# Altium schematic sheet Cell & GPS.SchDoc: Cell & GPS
size 431 x 279 mm; DocumentNumber: 10000020916; Revision: 000; SheetNumber: 8; SheetTotal: 10; ProjectTitle: Industrial IOT Sensor
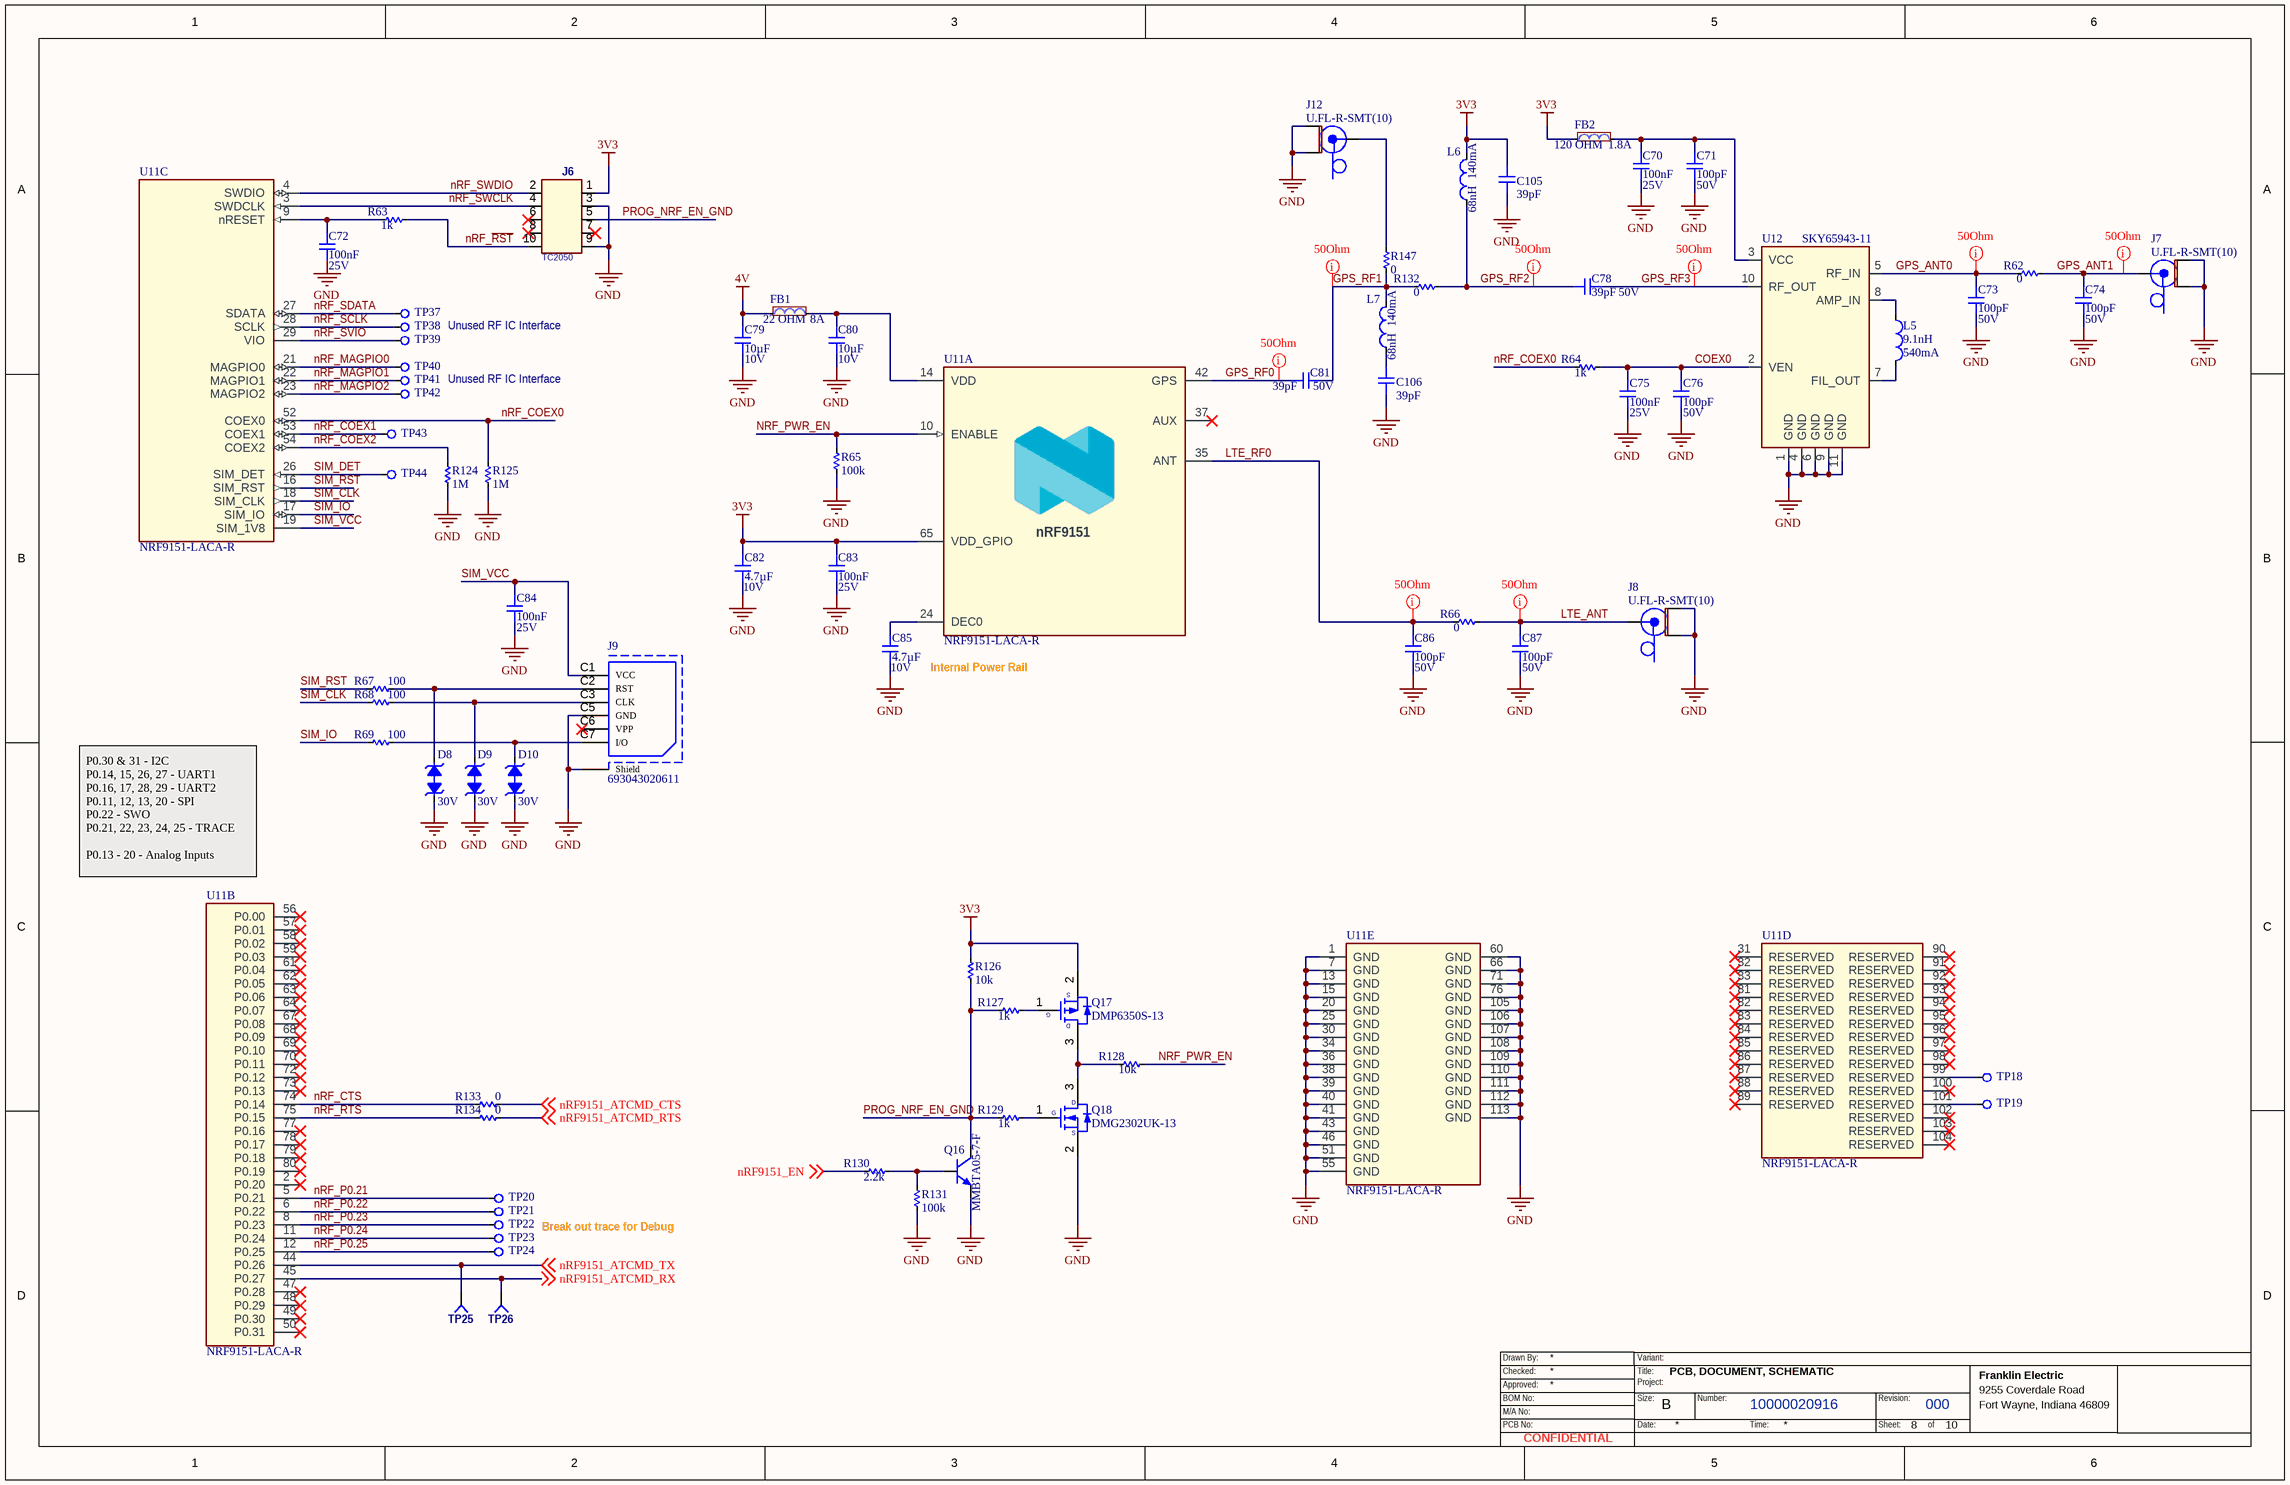
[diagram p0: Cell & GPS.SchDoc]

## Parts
C70  100nF  Voltage Rating DC: 25V  [CAPC1005X60N]
C71  100pF  Voltage Rating DC: 50V  [CAPC1005X60N]
C72  100nF  Voltage Rating DC: 25V  [CAPC1005X60N]
C73  100pF  Voltage Rating DC: 50V  [CAPC1005X60N]
C74  100pF  Voltage Rating DC: 50V  [CAPC1005X60N]
C75  100nF  Voltage Rating DC: 25V  [CAPC1005X60N]
C76  100pF  Voltage Rating DC: 50V  [CAPC1005X60N]
C78  39pF  Voltage Rating DC: 50V  [CAPC1005X60N]
C79  10µF  Voltage Rating DC: 10V  [CAPC1608X90N]
C80  10µF  Voltage Rating DC: 10V  [CAPC1608X90N]
C81  39pF  Voltage Rating DC: 50V  [CAPC1005X60N]
C82  4.7µF  Voltage Rating DC: 10V  [CAPC1005X60N]
C83  100nF  Voltage Rating DC: 25V  [CAPC1005X60N]
C84  100nF  Voltage Rating DC: 25V  [CAPC1005X60N]
C85  4.7µF  Voltage Rating DC: 10V  [CAPC1005X60N]
C86  100pF  Voltage Rating DC: 50V  [CAPC1005X60N]
C87  100pF  Voltage Rating DC: 50V  [CAPC1005X60N]
C105  39pF  [CAPC1005X60N]
C106  39pF  [CAPC1005X60N]
D8  Reverse Voltage: 30V  [SOD882-A]  (hidden comment: PESD30VF1BLYL)
D9  Reverse Voltage: 30V  [SOD882-A]  (hidden comment: PESD30VF1BLYL)
D10  Reverse Voltage: 30V  [SOD882-A]  (hidden comment: PESD30VF1BLYL)
FB1  22 OHM  Rated Current: 8A  [INDC1608X06N]
FB2  120 OHM  Rated Current: 1.8A  [FerriteBead_0402]
J6  value TC2050  [TC2050_NL]  (hidden comment: J_CONN TC2050)  (no BOM)
J7  U.FL-R-SMT(10)  [CONN U.FL RCPT]
J8  U.FL-R-SMT(10)  [CONN U.FL RCPT]
J9  693043020611  [Nano SIM Card]
J12  U.FL-R-SMT(10)  [CONN U.FL RCPT]
L5  9.1nH  Rated Current: 540mA  [IND0402-WIREWOUND-NO-MAGNETIC-N]
L6  68nH  Rated Current: 140mA  [IND0402-WIREWOUND-NO-MAGNETIC-N]
L7  68nH  Rated Current: 140mA  [IND0402-WIREWOUND-NO-MAGNETIC-N]
Q16  MMBTA05-7-F  [SOT90P225X100-3N]
Q17  DMP6350S-13  [SOT90P225X100-3N]
Q18  DMG2302UK-13  [SOT90P225X100-3N]
R62  0  [RESC1005N]
R63  1k  [RESC1005N]
R64  1k  [RESC1005N]
R65  100k  [RESC1005N]
R66  0  [RESC1005N]
R67  100  [RESC1005N]
R68  100  [RESC1005N]
R69  100  [RESC1005N]
R124  1M  [RESC1005N]
R125  1M  [RESC1005N]
R126  10k  [RESC1005N]
R127  1k  [RESC1005N]
R128  10k  [RESC1005N]
R129  1k  [RESC1005N]
R130  2.2k  [RESC1005N]
R131  100k  [RESC1005N]
R132  0  [RESC1005N]
R133  0  [RESC1005N]
R134  0  [RESC1005N]
R147  0  [RESC1005N]
TP18  Test Points  [TP040SMD]  (value not drawn)  (no BOM)
TP19  Test Points  [TP040SMD]  (value not drawn)  (no BOM)
TP20  Test Points  [TP040SMD]  (value not drawn)  (no BOM)
TP21  Test Points  [TP040SMD]  (value not drawn)  (no BOM)
TP22  Test Points  [TP040SMD]  (value not drawn)  (no BOM)
TP23  Test Points  [TP040SMD]  (value not drawn)  (no BOM)
TP24  Test Points  [TP040SMD]  (value not drawn)  (no BOM)
TP25  TEST POINT, SMD PAD, .050 DIA  [TESTPOINT_SMD_ROUND_50]  (value not drawn)
TP26  TEST POINT, SMD PAD, .050 DIA  [TESTPOINT_SMD_ROUND_50]  (value not drawn)
TP37  Test Points  [TP 10 Mils SMD]  (value not drawn)  (no BOM)
TP38  Test Points  [TP 10 Mils SMD]  (value not drawn)  (no BOM)
TP39  Test Points  [TP 10 Mils SMD]  (value not drawn)  (no BOM)
TP40  Test Points  [TP 10 Mils SMD]  (value not drawn)  (no BOM)
TP41  Test Points  [TP 10 Mils SMD]  (value not drawn)  (no BOM)
TP42  Test Points  [TP 10 Mils SMD]  (value not drawn)  (no BOM)
TP43  Test Points  [TP 10 Mils SMD]  (value not drawn)  (no BOM)
TP44  Test Points  [TP 10 Mils SMD]  (value not drawn)  (no BOM)
U11  NRF9151-LACA-R  [NRF9151-LACA-R]  (parts A,B,C,D,E of 5)
U12  SKY65943-11  [10-MCM (2.5x2.5)]

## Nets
3V3: C82.1 C83.1 C105.1 FB2.1 J6.1 L6.2 Q17.2(Source) R126.1 U11.65(VDD_GPIO)
4V: C79.1 FB1.1
GND: C70.2 C71.2 C72.2 C73.2 C74.2 C75.2 C76.2 C79.2 C80.2 C82.2 C83.2 C84.2 C85.2 C86.2 C87.2 C105.2 C106.2 D8.1(K1) D9.1(K1) D10.1(K1) J6.3 J6.9 J7.2(GND) J7.3(GND) J8.2(GND) J8.3(GND) J9.C5(GND) J9.Shield J12.2(GND) J12.3(GND) Q16.2(E) Q18.2(Source) R65.2 R124.2 R125.2 R131.2 U11.1(GND) U11.7(GND) U11.13(GND) U11.15(GND) U11.20(GND) U11.25(GND) U11.30(GND) U11.34(GND) U11.36(GND) U11.38(GND) U11.39(GND) U11.40(GND) U11.41(GND) U11.43(GND) U11.46(GND) U11.51(GND) U11.55(GND) U11.60(GND) U11.66(GND) U11.71(GND) U11.76(GND) U11.105(GND) U11.106(GND) U11.107(GND) U11.108(GND) U11.109(GND) U11.110(GND) U11.111(GND) U11.112(GND) U11.113(GND) U12.1(GND) U12.4(GND) U12.6(GND) U12.9(GND) U12.11(GND)
COEX0: C75.1 C76.1 R64.2 U12.2(VEN)
GPS_ANT0: C73.1 R62.1 U12.5(RF_IN)
GPS_ANT1: C74.1 J7.1(SIG) R62.2
GPS_RF0: C81.1 U11.42(GPS)
GPS_RF1: C81.2 L7.2 R132.1 R147.2
GPS_RF2: C78.1 L6.1 R132.2
GPS_RF3: C78.2 U12.10(RF_OUT)
LTE_ANT: C87.1 J8.1(SIG) R66.2
LTE_RF0: C86.1 R66.1 U11.35(ANT)
nRF9151_ATCMD_CTS: R133.2 ; off-sheet nRF9151_ATCMD_CTS
nRF9151_ATCMD_RTS: R134.2 ; off-sheet nRF9151_ATCMD_RTS
nRF9151_ATCMD_RX: TP26.1(TP) U11.45(P0.27) ; off-sheet nRF9151_ATCMD_RX
nRF9151_ATCMD_TX: TP25.1(TP) U11.44(P0.26) ; off-sheet nRF9151_ATCMD_TX
nRF9151_EN: R130.1 ; off-sheet nRF9151_EN
nRF_COEX0: R64.1 R125.1 U11.52(COEX0)
nRF_COEX1: TP43.1 U11.53(COEX1)
nRF_COEX2: R124.1 U11.54(COEX2)
nRF_CTS: R133.1 U11.74(P0.14)
nRF_MAGPIO0: TP40.1 U11.21(MAGPIO0)
nRF_MAGPIO1: TP41.1 U11.22(MAGPIO1)
nRF_MAGPIO2: TP42.1 U11.23(MAGPIO2)
nRF_P0.21: TP20.1 U11.5(P0.21)
nRF_P0.22: TP21.1 U11.6(P0.22)
nRF_P0.23: TP22.1 U11.8(P0.23)
nRF_P0.24: TP23.1 U11.11(P0.24)
nRF_P0.25: TP24.1 U11.12(P0.25)
NRF_PWR_EN: R65.1 R128.2 U11.10(ENABLE)
nRF_~{RST}: J6.10 R63.2
nRF_RTS: R134.1 U11.75(P0.15)
nRF_SCLK: TP38.1 U11.28(SCLK)
nRF_SDATA: TP37.1 U11.27(SDATA)
nRF_SVIO: TP39.1 U11.29(VIO)
nRF_SWCLK: J6.4 U11.3(SWDCLK)
nRF_SWDIO: J6.2 U11.4(SWDIO)
PROG_NRF_EN_GND: J6.5 Q16.3(C) R126.2 R127.1 R129.1
SIM_CLK: R68.1 U11.18(SIM_CLK)
SIM_DET: TP44.1 U11.26(SIM_DET)
SIM_IO: R69.1 U11.17(SIM_IO)
SIM_RST: R67.1 U11.16(SIM_RST)
SIM_VCC: C84.1 J9.C1(VCC) U11.19(SIM_1V8)
NetC70_1: C70.1 C71.1 FB2.2 U12.3
NetC72_1: C72.1 R63.1 U11.9(nRESET)
NetC80_1: C80.1 FB1.2 U11.14(VDD)
NetC85_1: C85.1 U11.24(DEC0)
NetC106_1: C106.1 L7.1
NetD8_2: D8.2(K2) J9.C2(RST) R67.2
NetD9_2: D9.2(K2) J9.C3(CLK) R68.2
NetD10_2: D10.2(K2) J9.C7(I/O) R69.2
NetJ12_1: J12.1(SIG) R147.1
NetL5_1: L5.1 U12.8(AMP_IN)
NetL5_2: L5.2 U12.7
NetQ16_1: Q16.1(B) R130.2 R131.1
NetQ17_1: Q17.1(Gate) R127.2
NetQ17_3: Q17.3(Drain) Q18.3(Drain) R128.1
NetQ18_1: Q18.1(Gate) R129.2
NetTP18_1: TP18.1 U11.99(RESERVED)
NetTP19_1: TP19.1 U11.101(RESERVED)

Not connected (* = marked no-connect by the designer): J6 6* 7* 8*; J9 C6(VPP)*; U11 2(P0.20)* 31(RESERVED)* 32(RESERVED)* 33(RESERVED)* 37(AUX)* 47(P0.28)* 48(P0.29)* 49(P0.30)* 50(P0.31)* 56(P0.00)* 57(P0.01)* 58(P0.02)* 59(P0.03)* 61(P0.04)* 62(P0.05)* 63(P0.06)* 64(P0.07)* 67(P0.08)* 68(P0.09)* 69(P0.10)* 70(P0.11)* 72(P0.12)* 73(P0.13)* 77(P0.16)* 78(P0.17)* 79(P0.18)* 80(P0.19)* 81(RESERVED)* 82(RESERVED)* 83(RESERVED)* 84(RESERVED)* 85(RESERVED)* 86(RESERVED)* 87(RESERVED)* 88(RESERVED)* 89(RESERVED)* 90(RESERVED)* 91(RESERVED)* 92(RESERVED)* 93(RESERVED)* 94(RESERVED)* 95(RESERVED)* 96(RESERVED)* 97(RESERVED)* 98(RESERVED)* 100(RESERVED)* 102(RESERVED)* 103(RESERVED)* 104(RESERVED)*; U12 12

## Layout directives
mark named 50Ohm: GPS_ANT0, GPS_ANT1, GPS_RF0, GPS_RF1, GPS_RF2, GPS_RF3, LTE_ANT, LTE_RF0

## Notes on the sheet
- Unused RF IC Interface
- Internal Power Rail
- (near U11) P0.30 & 31 - I2C
  P0.14, 15, 26, 27 - UART1
  P0.16, 17, 28, 29 - UART2
  P0.11, 12, 13, 20 - SPI
  P0.22 - SWO
  P0.21, 22, 23, 24, 25 - TRACE
  P0.13 - 20 - Analog Inputs
- Break out trace for Debug

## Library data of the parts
C70 C72 C75 C83 C84 = CMP-00599-2: CAP CER SMD 0402 (1005) 25V 10% 0.1UF X7R; MFR2PN: 04023C104KAT2A; MFR1PN: CGA2B3X7R1E104K; MFR3PN: CL05B104KA5NNNC; MFR1: TDK; MFR4PN: TMK105B7104KVHF; FEPN: 228685108; Agency Restriction: N; Op Temp Min: -55°C; Op Temp Max: 125°C; Voltage Rating AC: 0V
C71 C73 C74 C76 C86 C87 = CMP-01679-1: CAP CER SMD 0402 50V 2% 100pF C0G; MFR1: MURATA; MFR1PN: GRM1555C1H101GA01D; FEPN: 10000022639; Op Temp Max: 125°C; Op Temp Min: -55°C; Agency Restriction: None
C78 C81 C105 C106 = CMP-01680-1: CAP CER SMD 0402 50V 1% 39pF C0G; MFR1: MURATA; MFR1PN: GCM1555C1H390FA16D; Op Temp Max: 125°C; Agency Restriction: None; FEPN: 10000022640; Op Temp Min: -55°C
C79 C80 = CMP-003-0109-42: CAP CER SMD 0603 10V 10% 10uF X5R; MFR1: Murata; MFR2PN: CL10A106KP8NNND; MFR3PN: 0603X106K100CT; MFR1PN: GRM188R61A106KE69D; FEPN: 227000148; Op Temp Max: 85°C; Agency Restriction: No; Op Temp Min: -55°C
C82 C85 = CMP-01681-2: CAP CER SMD 0402 10V 10% 4.7uF X5R; MFR1: TDK; MFR1PN: C1005X5R1A475K050BC; Op Temp Min: -55°C; Agency Restriction: None; FEPN: 10000022641; Op Temp Max: 85°C
D8-D10 = CMP-01699-5: SURGE SUPPRESSOR, TVS, SMD 30V 16A SOD-882; MFR1: NEXPERIA; Op Temp Min: -55°C; Op Temp Max: 150°C; FEPN: 10000022897; Agency Restriction: NA; Forward Voltage: 23V
FB1 = CMP-01706-3: INDUCTOR, FERRITE BEAD, SMD 22 OHM 5A 0603 1LN; MFR1PN: BLM18SN220TN1D; MFR1: MURATA; Value: 0µH; FEPN: 10000023002; Agency Restriction: N; Op Temp Min: -55°C; Tolerance: 0%; Op Temp Max: 125°C; Type: Drum Core, Wirewound; Saturation Current: 0A
FB2 = CMP-01756-2: INDUCTOR, FERRITE BEAD, SMD 120 OHM 1.2A 0402 1LN; MFR1PN: BLM15EX121SN1D; MFR1: MURATA; Saturation Current: 0A; Op Temp Min: -55°C; FEPN: 10000023684; Tolerance: 0%; Value: 0µH; Op Temp Max: 125°C; Agency Restriction: None
J6 = J_CONN TC2050: DNA - TC2030-MCP Plug-of-Nails Programming Terminals (PCB Feature)(Do Not Assemble); Part_Type: Miscellaneous; FPLIST: TC2030,TC2030_SP
J7 J8 = CMP-01738-3: CONNECTOR, COAXIAL RF, RCPT STR 50 OHM SMD; MFR2PN: 2337019-1; MFR1: HIROSE; Op Temp Max: 90°C; Agency Restriction: None; FEPN: 10000023423; Voltage Rating: 0V; Current Rated: 16A; Number Of Positions: 1; Current Rating: 0A; Op Temp Min: -40°C
J9 = CMP-01739-4: CONNECTOR NANO SIM CARD R/A SMD; MFR1: WURTH; Voltage Rating: 0V; Current Rating: 0A; Op Temp Max: 0°C; Agency Restriction: None; Number Of Positions: 6; FEPN: 10000023424
J12 = CMP-01738-3: CONNECTOR, COAXIAL RF, RCPT STR 50 OHM SMD; MFR1: HIROSE; MFR2PN: 2337019-1; Op Temp Max: 90°C; FEPN: 10000023423; Voltage Rating: 0V; Op Temp Min: -40°C; Current Rated: 16A; Agency Restriction: None; Current Rating: 0A; Number Of Positions: 1
L5 = CMP-01704-2: INDUCTOR, FIXED, SURFACE MOUNT 9.1nH 540mA 140mOHM; MFR1PN: LQW15AN9N1G00D; MFR1: MURATA; Op Temp Min: -55°C; Saturation Current: 0A; Agency Restriction: N; Op Temp Max: 125°C; Tolerance: 2%; FEPN: 10000023001; Type: Drum Core, Wirewound
L6 L7 = CMP-01757-3: INDUCTOR, FIXED, SURFACE MOUNT 68nH 140mA 1.96 OHM; MFR1PN: LQW15AN68NG00D; MFR1: MURATA; FEPN: 10000023685; Tolerance: 0%; Op Temp Max: 125°C; Agency Restriction: N; Saturation Current: 0A; Op Temp Min: -55°C
Q16 = CMP-01727-3: TRANSISTOR, BIPOLAR, NPN 60V 0.5A SOT23 SMD; MFR1: DIODES INC; Agency Restriction: N; Op Temp Max: 150°C; Op Temp Min: -55°C; Current Rating: 500mA; FEPN: 10000023200
Q17 = CMP-01723-2: TRANSISTOR, FET/MOSFET, P 60V 1.5A SOT23 SMD; MFR1: DIODES INC; FEPN: 10000023199; Op Temp Max: 150°C; Op Temp Min: -55°C; Type: MOSFET; Agency Restriction: N
Q18 = CMP-01724-2: TRANSISTOR, FET, N 20V 2.8A SOT23 SMD; MFR1: DIODES INC; Type: MOSFET; FEPN: 10000023201; Op Temp Min: -55°C; Op Temp Max: 150°C
R62 R66 R132-R134 R147 = CMP-01604-3: RESISTOR, SMD, THCK FLM ASR 0402 100mW 1% 0 OHM; MFR1PN: ERJ-U020R00X; MFR1: PANASONIC; Op Temp Max: 155°C; FEPN: 10000021231; Agency Restriction: None; Temperature Coefficient: ±200ppm/°C; Op Temp Min: -55°C
R63 R64 R127 R129 = CMP-01603-4: RESISTOR, SMD, THN FLM ASR 0402 100mW 1% 1K OHM; MFR1: STACKPOLE; MFR1PN: RNCP0402FTD1K00; Op Temp Max: 155°C; FEPN: 10000021229; Temperature Coefficient: ±200ppm/°C; Agency Restriction: None; Op Temp Min: -55°C
R65 R131 = CMP-01591-4: RESISTOR, SMD, THCK FLM ASR 0402 100mW 1% 100K OHM; MFR1: PANASONIC; MFR1PN: ERJ-U02F1003X; FEPN: 10000021214; Agency Restriction: None; Op Temp Max: 155°C; Op Temp Min: -55°C; Temperature Coefficient: ±200ppm/°C
R67-R69 = CMP-01605-4: RESISTOR, SMD, THCK FLM ASR 0402 100mW 1% 100 OHM; MFR1: PANASONIC; MFR1PN: ERJ-U02F1000X; Op Temp Min: -55°C; Op Temp Max: 155°C; Temperature Coefficient: ±200ppm/°C; Agency Restriction: None; FEPN: 10000021232
R124 R125 = CMP-01751-1: RESISTOR, SMD, THCK FLM ASR 0402 100mW 1% 1M OHM; MFR1: PANASONIC; MFR1PN: ERJ-S02F1004X; Op Temp Min: -55°C; Op Temp Max: 155°C; FEPN: 10000023680; Agency Restriction: None; Temperature Coefficient: ±200ppm/°C
R126 R128 = CMP-01594-4: RESISTOR, SMD, THCK FLM ASR 0402 100mW 1% 10K OHM; MFR1PN: RNCP0402FTD10K0; MFR1: STACKPOLE; Agency Restriction: None; Op Temp Min: -55°C; FEPN: 10000021217; Temperature Coefficient: ±200ppm/°C; Op Temp Max: 155°C
R130 = CMP-01750-1: RESISTOR, SMD, THCK FLM ASR 0402 100mW 1% 2.2k OHM; MFR1PN: ERJ-U02F2201X; MFR1: PANASONIC; Agency Restriction: None; Temperature Coefficient: ±200ppm/°C; Op Temp Min: -55°C; FEPN: 10000023679; Op Temp Max: 155°C
TP18-TP24 TP37-TP44 = CMP-ROOT-0001-.61
TP25 TP26 = TEST POINT, SMD PAD, .050 DIA: TESTPOINT, SMD PAD, .050 DIA; Placement: NP
U11 = CMP-01748-3: MODULE, OTHER RF TXRX + MCU CELL; MFR1: NORDIC SEMI; Op Temp Min: 0°C; FEPN: 10000023438; Agency Restriction: N
U12 = CMP-01749-2: MODULE, OTHER GPS LNA; MFR1: Skyworks Solutions; FEPN: 10000023440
